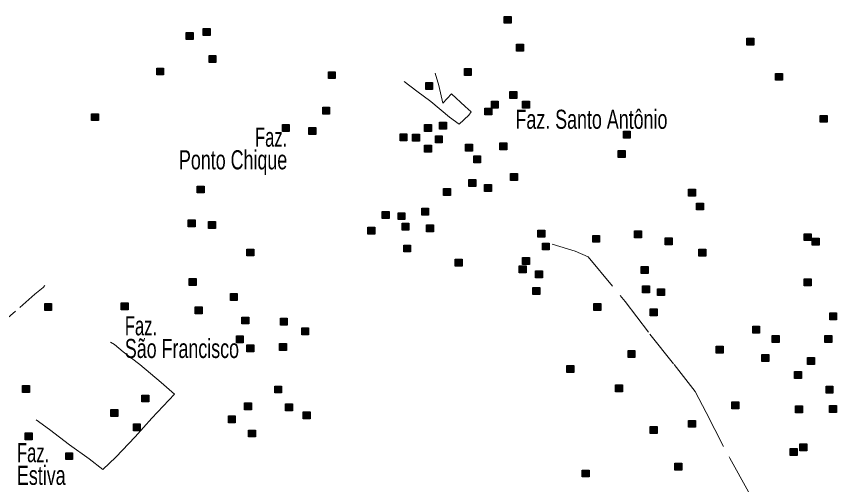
# Model space of a CAD drawing. Extents: x 445.6 to 500, y 8618.1 to 8673.4.
# Drawn here: x 456.65 to 463.53, y 8640.26 to 8644.2 of the extents above; entities that cross this region are included whole.
import ezdxf
from ezdxf.enums import TextEntityAlignment as Align

# ---------------------------------------------------------------- set-up
doc = ezdxf.new("R2010")
doc.units = 0
doc.header["$LTSCALE"] = 0.064
doc.linetypes.add('DOT_DASHED', pattern=[7.7, 5, -1.2, 0.3, -1.2])
doc.layers.add('2', color=7, linetype='Continuous', lineweight=25)
doc.layers.add('22', color=7, linetype='DOT_DASHED', lineweight=13)
doc.layers.add('61', color=7, linetype='Continuous')

msp = doc.modelspace()

# ---------------------------------------------------------------- hatches: boundary and pattern name
at = {"layer": '2'}
for points in [[(460.7425, 8644.196), (460.8005, 8644.196), (460.8005, 8644.138), (460.7425, 8644.138)], [(458.0774, 8644.0607), (458.1354, 8644.0607), (458.1354, 8644.0027), (458.0774, 8644.0027)], [(458.2193, 8644.0946), (458.2773, 8644.0946), (458.2773, 8644.0366), (458.2193, 8644.0366)], [(462.7768, 8644.0124), (462.8348, 8644.0124), (462.8348, 8643.9544), (462.7768, 8643.9544)], [(460.846, 8643.9624), (460.904, 8643.9624), (460.904, 8643.9044), (460.846, 8643.9044)], [(458.2681, 8643.8678), (458.3261, 8643.8678), (458.3261, 8643.8098), (458.2681, 8643.8098)], [(457.8289, 8643.7628), (457.8869, 8643.7628), (457.8869, 8643.7048), (457.8289, 8643.7048)], [(460.4086, 8643.7592), (460.4666, 8643.7592), (460.4666, 8643.7012), (460.4086, 8643.7012)], [(459.2679, 8643.7323), (459.3259, 8643.7323), (459.3259, 8643.6743), (459.2679, 8643.6743)], [(463.0168, 8643.7185), (463.0748, 8643.7185), (463.0748, 8643.6605), (463.0168, 8643.6605)], [(460.0843, 8643.6406), (460.1423, 8643.6406), (460.1423, 8643.5826), (460.0843, 8643.5826)], [(460.7903, 8643.5661), (460.8483, 8643.5661), (460.8483, 8643.5081), (460.7903, 8643.5081)], [(460.6349, 8643.4848), (460.6929, 8643.4848), (460.6929, 8643.4268), (460.6349, 8643.4268)], [(460.8967, 8643.4847), (460.9547, 8643.4847), (460.9547, 8643.4267), (460.8967, 8643.4267)], [(459.2206, 8643.4341), (459.2786, 8643.4341), (459.2786, 8643.3761), (459.2206, 8643.3761)], [(460.5808, 8643.4272), (460.6388, 8643.4272), (460.6388, 8643.3692), (460.5808, 8643.3692)], [(457.2832, 8643.3799), (457.3412, 8643.3799), (457.3412, 8643.3219), (457.2832, 8643.3219)], [(463.3918, 8643.3662), (463.4498, 8643.3662), (463.4498, 8643.3082), (463.3918, 8643.3082)], [(458.8828, 8643.2885), (458.9408, 8643.2885), (458.9408, 8643.2305), (458.8828, 8643.2305)], [(460.0742, 8643.2883), (460.1322, 8643.2883), (460.1322, 8643.2303), (460.0742, 8643.2303)], [(460.1992, 8643.3086), (460.2572, 8643.3086), (460.2572, 8643.2506), (460.1992, 8643.2506)], [(459.1057, 8643.2647), (459.1637, 8643.2647), (459.1637, 8643.2067), (459.1057, 8643.2067)], [(459.8691, 8643.2105), (459.9271, 8643.2105), (459.9271, 8643.1525), (459.8691, 8643.1525)], [(459.9743, 8643.2086), (460.0323, 8643.2086), (460.0323, 8643.1506), (459.9743, 8643.1506)], [(461.7411, 8643.234), (461.7991, 8643.234), (461.7991, 8643.176), (461.7411, 8643.176)], [(460.1654, 8643.1934), (460.2234, 8643.1934), (460.2234, 8643.1354), (460.1654, 8643.1354)], [(460.0742, 8643.1155), (460.1322, 8643.1155), (460.1322, 8643.0575), (460.0742, 8643.0575)], [(460.4189, 8643.1237), (460.4769, 8643.1237), (460.4769, 8643.0657), (460.4189, 8643.0657)], [(460.7058, 8643.1358), (460.7638, 8643.1358), (460.7638, 8643.0778), (460.7058, 8643.0778)], [(461.6972, 8643.0714), (461.7552, 8643.0714), (461.7552, 8643.0134), (461.6972, 8643.0134)], [(460.4865, 8643.0254), (460.5445, 8643.0254), (460.5445, 8642.9674), (460.4865, 8642.9674)], [(460.7954, 8642.8783), (460.8534, 8642.8783), (460.8534, 8642.8203), (460.7954, 8642.8203)], [(460.4457, 8642.8275), (460.5037, 8642.8275), (460.5037, 8642.7695), (460.4457, 8642.7695)], [(458.1681, 8642.7734), (458.2261, 8642.7734), (458.2261, 8642.7154), (458.1681, 8642.7154)], [(460.2329, 8642.753), (460.2909, 8642.753), (460.2909, 8642.695), (460.2329, 8642.695)], [(460.5775, 8642.7869), (460.6355, 8642.7869), (460.6355, 8642.7289), (460.5775, 8642.7289)], [(462.2873, 8642.7462), (462.3453, 8642.7462), (462.3453, 8642.6882), (462.2873, 8642.6882)], [(462.3548, 8642.631), (462.4128, 8642.631), (462.4128, 8642.573), (462.3548, 8642.573)], [(459.7205, 8642.5601), (459.7785, 8642.5601), (459.7785, 8642.5021), (459.7205, 8642.5021)], [(459.8522, 8642.5499), (459.9102, 8642.5499), (459.9102, 8642.4919), (459.8522, 8642.4919)], [(460.0505, 8642.587), (460.1085, 8642.587), (460.1085, 8642.529), (460.0505, 8642.529)], [(458.0938, 8642.4889), (458.1518, 8642.4889), (458.1518, 8642.4309), (458.0938, 8642.4309)], [(458.2627, 8642.4753), (458.3207, 8642.4753), (458.3207, 8642.4173), (458.2627, 8642.4173)], [(459.886, 8642.4618), (459.944, 8642.4618), (459.944, 8642.4038), (459.886, 8642.4038)], [(459.5989, 8642.4279), (459.6569, 8642.4279), (459.6569, 8642.3699), (459.5989, 8642.3699)], [(460.0911, 8642.4481), (460.1491, 8642.4481), (460.1491, 8642.3901), (460.0911, 8642.3901)], [(461.025, 8642.404), (461.083, 8642.404), (461.083, 8642.346), (461.025, 8642.346)], [(461.8357, 8642.3972), (461.8937, 8642.3972), (461.8937, 8642.3392), (461.8357, 8642.3392)], [(461.4844, 8642.36), (461.5424, 8642.36), (461.5424, 8642.302), (461.4844, 8642.302)], [(462.0913, 8642.3396), (462.1493, 8642.3396), (462.1493, 8642.2816), (462.0913, 8642.2816)], [(463.2567, 8642.3735), (463.3147, 8642.3735), (463.3147, 8642.3155), (463.2567, 8642.3155)], [(463.3242, 8642.3362), (463.3822, 8642.3362), (463.3822, 8642.2782), (463.3242, 8642.2782)], [(458.5856, 8642.245), (458.6436, 8642.245), (458.6436, 8642.187), (458.5856, 8642.187)], [(459.8995, 8642.2789), (459.9575, 8642.2789), (459.9575, 8642.2209), (459.8995, 8642.2209)], [(461.0622, 8642.2956), (461.1202, 8642.2956), (461.1202, 8642.2376), (461.0622, 8642.2376)], [(462.3751, 8642.2448), (462.4331, 8642.2448), (462.4331, 8642.1868), (462.3751, 8642.1868)], [(460.3309, 8642.1601), (460.3889, 8642.1601), (460.3889, 8642.1021), (460.3309, 8642.1021)], [(460.8967, 8642.1736), (460.9547, 8642.1736), (460.9547, 8642.1156), (460.8967, 8642.1156)], [(460.8687, 8642.1031), (460.9267, 8642.1031), (460.9267, 8642.0451), (460.8687, 8642.0451)], [(461.0048, 8642.0618), (461.0628, 8642.0618), (461.0628, 8642.0038), (461.0048, 8642.0038)], [(461.8917, 8642.0994), (461.9497, 8642.0994), (461.9497, 8642.0414), (461.8917, 8642.0414)], [(458.1021, 8641.9977), (458.1601, 8641.9977), (458.1601, 8641.9397), (458.1021, 8641.9397)], [(463.257, 8641.994), (463.315, 8641.994), (463.315, 8641.936), (463.257, 8641.936)], [(460.983, 8641.9228), (461.041, 8641.9228), (461.041, 8641.8648), (460.983, 8641.8648)], [(461.9019, 8641.9365), (461.9599, 8641.9365), (461.9599, 8641.8785), (461.9019, 8641.8785)], [(462.0269, 8641.9128), (462.0849, 8641.9128), (462.0849, 8641.8548), (462.0269, 8641.8548)], [(458.4466, 8641.8724), (458.5046, 8641.8724), (458.5046, 8641.8144), (458.4466, 8641.8144)], [(456.8904, 8641.7877), (456.9484, 8641.7877), (456.9484, 8641.7297), (456.8904, 8641.7297)], [(457.5322, 8641.7944), (457.5902, 8641.7944), (457.5902, 8641.7364), (457.5322, 8641.7364)], [(461.4932, 8641.7875), (461.5512, 8641.7875), (461.5512, 8641.7295), (461.4932, 8641.7295)], [(458.1528, 8641.7606), (458.2108, 8641.7606), (458.2108, 8641.7026), (458.1528, 8641.7026)], [(461.9652, 8641.743), (462.0232, 8641.743), (462.0232, 8641.685), (461.9652, 8641.685)], [(463.4708, 8641.7097), (463.5288, 8641.7097), (463.5288, 8641.6517), (463.4708, 8641.6517)], [(458.5434, 8641.6752), (458.6014, 8641.6752), (458.6014, 8641.6172), (458.5434, 8641.6172)], [(458.8655, 8641.6657), (458.9235, 8641.6657), (458.9235, 8641.6077), (458.8655, 8641.6077)], [(459.0445, 8641.5844), (459.1025, 8641.5844), (459.1025, 8641.5264), (459.0445, 8641.5264)], [(462.8257, 8641.5979), (462.8837, 8641.5979), (462.8837, 8641.5399), (462.8257, 8641.5399)], [(458.4973, 8641.5166), (458.5553, 8641.5166), (458.5553, 8641.4586), (458.4973, 8641.4586)], [(462.9895, 8641.5198), (463.0475, 8641.5198), (463.0475, 8641.4618), (462.9895, 8641.4618)], [(463.4303, 8641.5199), (463.4883, 8641.5199), (463.4883, 8641.4619), (463.4303, 8641.4619)], [(458.584, 8641.4412), (458.642, 8641.4412), (458.642, 8641.3832), (458.584, 8641.3832)], [(458.8587, 8641.4523), (458.9167, 8641.4523), (458.9167, 8641.3943), (458.8587, 8641.3943)], [(462.5198, 8641.431), (462.5778, 8641.431), (462.5778, 8641.373), (462.5198, 8641.373)], [(461.7803, 8641.3945), (461.8383, 8641.3945), (461.8383, 8641.3365), (461.7803, 8641.3365)], [(462.9034, 8641.3607), (462.9614, 8641.3607), (462.9614, 8641.3027), (462.9034, 8641.3027)], [(463.2846, 8641.3354), (463.3426, 8641.3354), (463.3426, 8641.2774), (463.2846, 8641.2774)], [(461.2669, 8641.2691), (461.3249, 8641.2691), (461.3249, 8641.2111), (461.2669, 8641.2111)], [(463.1753, 8641.2183), (463.2333, 8641.2183), (463.2333, 8641.1603), (463.1753, 8641.1603)], [(456.7046, 8641.0999), (456.7626, 8641.0999), (456.7626, 8641.0419), (456.7046, 8641.0419)], [(458.8182, 8641.0965), (458.8762, 8641.0965), (458.8762, 8641.0385), (458.8182, 8641.0385)], [(461.6756, 8641.1065), (461.7336, 8641.1065), (461.7336, 8641.0485), (461.6756, 8641.0485)], [(463.44, 8641.0948), (463.498, 8641.0948), (463.498, 8641.0368), (463.44, 8641.0368)], [(457.7048, 8641.0206), (457.7628, 8641.0206), (457.7628, 8640.9626), (457.7048, 8640.9626)], [(458.5649, 8640.9543), (458.6229, 8640.9543), (458.6229, 8640.8963), (458.5649, 8640.8963)], [(458.9094, 8640.9475), (458.9674, 8640.9475), (458.9674, 8640.8895), (458.9094, 8640.8895)], [(462.6518, 8640.9642), (462.7098, 8640.9642), (462.7098, 8640.9062), (462.6518, 8640.9062)], [(457.4444, 8640.8985), (457.5024, 8640.8985), (457.5024, 8640.8405), (457.4444, 8640.8405)], [(459.058, 8640.8797), (459.116, 8640.8797), (459.116, 8640.8217), (459.058, 8640.8217)], [(463.1855, 8640.9303), (463.2435, 8640.9303), (463.2435, 8640.8723), (463.1855, 8640.8723)], [(463.4704, 8640.9322), (463.5284, 8640.9322), (463.5284, 8640.8742), (463.4704, 8640.8742)], [(458.4298, 8640.8458), (458.4878, 8640.8458), (458.4878, 8640.7878), (458.4298, 8640.7878)], [(462.287, 8640.8084), (462.345, 8640.8084), (462.345, 8640.7504), (462.287, 8640.7504)], [(457.6335, 8640.7781), (457.6915, 8640.7781), (457.6915, 8640.7201), (457.6335, 8640.7201)], [(461.9671, 8640.756), (462.0251, 8640.756), (462.0251, 8640.698), (461.9671, 8640.698)], [(456.7266, 8640.7046), (456.7846, 8640.7046), (456.7846, 8640.6466), (456.7266, 8640.6466)], [(458.5986, 8640.7273), (458.6566, 8640.7273), (458.6566, 8640.6693), (458.5986, 8640.6693)], [(463.2209, 8640.612), (463.2789, 8640.612), (463.2789, 8640.554), (463.2209, 8640.554)], [(457.0661, 8640.5375), (457.1241, 8640.5375), (457.1241, 8640.4795), (457.0661, 8640.4795)], [(463.1398, 8640.5713), (463.1978, 8640.5713), (463.1978, 8640.5133), (463.1398, 8640.5133)], [(461.3952, 8640.3919), (461.4532, 8640.3919), (461.4532, 8640.3339), (461.3952, 8640.3339)], [(462.1721, 8640.4493), (462.2301, 8640.4493), (462.2301, 8640.3913), (462.1721, 8640.3913)]]:
    msp.add_hatch(color=256, dxfattribs=at).paths.add_polyline_path(points)

# ---------------------------------------------------------------- linework, layer by layer
for points in [[(460.7425, 8644.196), (460.8005, 8644.196), (460.8005, 8644.138), (460.7425, 8644.138)], [(458.0774, 8644.0607), (458.1354, 8644.0607), (458.1354, 8644.0027), (458.0774, 8644.0027)], [(458.2193, 8644.0946), (458.2773, 8644.0946), (458.2773, 8644.0366), (458.2193, 8644.0366)], [(462.7768, 8644.0124), (462.8348, 8644.0124), (462.8348, 8643.9544), (462.7768, 8643.9544)], [(460.846, 8643.9624), (460.904, 8643.9624), (460.904, 8643.9044), (460.846, 8643.9044)], [(458.2681, 8643.8678), (458.3261, 8643.8678), (458.3261, 8643.8098), (458.2681, 8643.8098)], [(457.8289, 8643.7628), (457.8869, 8643.7628), (457.8869, 8643.7048), (457.8289, 8643.7048)], [(460.4086, 8643.7592), (460.4666, 8643.7592), (460.4666, 8643.7012), (460.4086, 8643.7012)], [(459.2679, 8643.7323), (459.3259, 8643.7323), (459.3259, 8643.6743), (459.2679, 8643.6743)], [(463.0168, 8643.7185), (463.0748, 8643.7185), (463.0748, 8643.6605), (463.0168, 8643.6605)], [(460.0843, 8643.6406), (460.1423, 8643.6406), (460.1423, 8643.5826), (460.0843, 8643.5826)], [(460.7903, 8643.5661), (460.8483, 8643.5661), (460.8483, 8643.5081), (460.7903, 8643.5081)], [(460.6349, 8643.4848), (460.6929, 8643.4848), (460.6929, 8643.4268), (460.6349, 8643.4268)], [(460.8967, 8643.4847), (460.9547, 8643.4847), (460.9547, 8643.4267), (460.8967, 8643.4267)], [(459.2206, 8643.4341), (459.2786, 8643.4341), (459.2786, 8643.3761), (459.2206, 8643.3761)], [(460.5808, 8643.4272), (460.6388, 8643.4272), (460.6388, 8643.3692), (460.5808, 8643.3692)], [(457.2832, 8643.3799), (457.3412, 8643.3799), (457.3412, 8643.3219), (457.2832, 8643.3219)], [(463.3918, 8643.3662), (463.4498, 8643.3662), (463.4498, 8643.3082), (463.3918, 8643.3082)], [(458.8828, 8643.2885), (458.9408, 8643.2885), (458.9408, 8643.2305), (458.8828, 8643.2305)], [(460.0742, 8643.2883), (460.1322, 8643.2883), (460.1322, 8643.2303), (460.0742, 8643.2303)], [(460.1992, 8643.3086), (460.2572, 8643.3086), (460.2572, 8643.2506), (460.1992, 8643.2506)], [(459.1057, 8643.2647), (459.1637, 8643.2647), (459.1637, 8643.2067), (459.1057, 8643.2067)], [(459.8691, 8643.2105), (459.9271, 8643.2105), (459.9271, 8643.1525), (459.8691, 8643.1525)], [(459.9743, 8643.2086), (460.0323, 8643.2086), (460.0323, 8643.1506), (459.9743, 8643.1506)], [(461.7411, 8643.234), (461.7991, 8643.234), (461.7991, 8643.176), (461.7411, 8643.176)], [(460.1654, 8643.1934), (460.2234, 8643.1934), (460.2234, 8643.1354), (460.1654, 8643.1354)], [(460.0742, 8643.1155), (460.1322, 8643.1155), (460.1322, 8643.0575), (460.0742, 8643.0575)], [(460.4189, 8643.1237), (460.4769, 8643.1237), (460.4769, 8643.0657), (460.4189, 8643.0657)], [(460.7058, 8643.1358), (460.7638, 8643.1358), (460.7638, 8643.0778), (460.7058, 8643.0778)], [(461.6972, 8643.0714), (461.7552, 8643.0714), (461.7552, 8643.0134), (461.6972, 8643.0134)], [(460.4865, 8643.0254), (460.5445, 8643.0254), (460.5445, 8642.9674), (460.4865, 8642.9674)], [(460.7954, 8642.8783), (460.8534, 8642.8783), (460.8534, 8642.8203), (460.7954, 8642.8203)], [(460.4457, 8642.8275), (460.5037, 8642.8275), (460.5037, 8642.7695), (460.4457, 8642.7695)], [(458.1681, 8642.7734), (458.2261, 8642.7734), (458.2261, 8642.7154), (458.1681, 8642.7154)], [(460.2329, 8642.753), (460.2909, 8642.753), (460.2909, 8642.695), (460.2329, 8642.695)], [(460.5775, 8642.7869), (460.6355, 8642.7869), (460.6355, 8642.7289), (460.5775, 8642.7289)], [(462.2873, 8642.7462), (462.3453, 8642.7462), (462.3453, 8642.6882), (462.2873, 8642.6882)], [(462.3548, 8642.631), (462.4128, 8642.631), (462.4128, 8642.573), (462.3548, 8642.573)], [(459.7205, 8642.5601), (459.7785, 8642.5601), (459.7785, 8642.5021), (459.7205, 8642.5021)], [(459.8522, 8642.5499), (459.9102, 8642.5499), (459.9102, 8642.4919), (459.8522, 8642.4919)], [(460.0505, 8642.587), (460.1085, 8642.587), (460.1085, 8642.529), (460.0505, 8642.529)], [(458.0938, 8642.4889), (458.1518, 8642.4889), (458.1518, 8642.4309), (458.0938, 8642.4309)], [(458.2627, 8642.4753), (458.3207, 8642.4753), (458.3207, 8642.4173), (458.2627, 8642.4173)], [(459.886, 8642.4618), (459.944, 8642.4618), (459.944, 8642.4038), (459.886, 8642.4038)], [(459.5989, 8642.4279), (459.6569, 8642.4279), (459.6569, 8642.3699), (459.5989, 8642.3699)], [(460.0911, 8642.4481), (460.1491, 8642.4481), (460.1491, 8642.3901), (460.0911, 8642.3901)], [(461.025, 8642.404), (461.083, 8642.404), (461.083, 8642.346), (461.025, 8642.346)], [(461.8357, 8642.3972), (461.8937, 8642.3972), (461.8937, 8642.3392), (461.8357, 8642.3392)], [(461.4844, 8642.36), (461.5424, 8642.36), (461.5424, 8642.302), (461.4844, 8642.302)], [(462.0913, 8642.3396), (462.1493, 8642.3396), (462.1493, 8642.2816), (462.0913, 8642.2816)], [(463.2567, 8642.3735), (463.3147, 8642.3735), (463.3147, 8642.3155), (463.2567, 8642.3155)], [(463.3242, 8642.3362), (463.3822, 8642.3362), (463.3822, 8642.2782), (463.3242, 8642.2782)], [(458.5856, 8642.245), (458.6436, 8642.245), (458.6436, 8642.187), (458.5856, 8642.187)], [(459.8995, 8642.2789), (459.9575, 8642.2789), (459.9575, 8642.2209), (459.8995, 8642.2209)], [(461.0622, 8642.2956), (461.1202, 8642.2956), (461.1202, 8642.2376), (461.0622, 8642.2376)], [(462.3751, 8642.2448), (462.4331, 8642.2448), (462.4331, 8642.1868), (462.3751, 8642.1868)], [(460.3309, 8642.1601), (460.3889, 8642.1601), (460.3889, 8642.1021), (460.3309, 8642.1021)], [(460.8967, 8642.1736), (460.9547, 8642.1736), (460.9547, 8642.1156), (460.8967, 8642.1156)], [(460.8687, 8642.1031), (460.9267, 8642.1031), (460.9267, 8642.0451), (460.8687, 8642.0451)], [(461.0048, 8642.0618), (461.0628, 8642.0618), (461.0628, 8642.0038), (461.0048, 8642.0038)], [(461.8917, 8642.0994), (461.9497, 8642.0994), (461.9497, 8642.0414), (461.8917, 8642.0414)], [(458.1021, 8641.9977), (458.1601, 8641.9977), (458.1601, 8641.9397), (458.1021, 8641.9397)], [(463.257, 8641.994), (463.315, 8641.994), (463.315, 8641.936), (463.257, 8641.936)], [(460.983, 8641.9228), (461.041, 8641.9228), (461.041, 8641.8648), (460.983, 8641.8648)], [(461.9019, 8641.9365), (461.9599, 8641.9365), (461.9599, 8641.8785), (461.9019, 8641.8785)], [(462.0269, 8641.9128), (462.0849, 8641.9128), (462.0849, 8641.8548), (462.0269, 8641.8548)], [(458.4466, 8641.8724), (458.5046, 8641.8724), (458.5046, 8641.8144), (458.4466, 8641.8144)], [(456.8904, 8641.7877), (456.9484, 8641.7877), (456.9484, 8641.7297), (456.8904, 8641.7297)], [(457.5322, 8641.7944), (457.5902, 8641.7944), (457.5902, 8641.7364), (457.5322, 8641.7364)], [(461.4932, 8641.7875), (461.5512, 8641.7875), (461.5512, 8641.7295), (461.4932, 8641.7295)], [(458.1528, 8641.7606), (458.2108, 8641.7606), (458.2108, 8641.7026), (458.1528, 8641.7026)], [(461.9652, 8641.743), (462.0232, 8641.743), (462.0232, 8641.685), (461.9652, 8641.685)], [(463.4708, 8641.7097), (463.5288, 8641.7097), (463.5288, 8641.6517), (463.4708, 8641.6517)], [(458.5434, 8641.6752), (458.6014, 8641.6752), (458.6014, 8641.6172), (458.5434, 8641.6172)], [(458.8655, 8641.6657), (458.9235, 8641.6657), (458.9235, 8641.6077), (458.8655, 8641.6077)], [(459.0445, 8641.5844), (459.1025, 8641.5844), (459.1025, 8641.5264), (459.0445, 8641.5264)], [(462.8257, 8641.5979), (462.8837, 8641.5979), (462.8837, 8641.5399), (462.8257, 8641.5399)], [(458.4973, 8641.5166), (458.5553, 8641.5166), (458.5553, 8641.4586), (458.4973, 8641.4586)], [(462.9895, 8641.5198), (463.0475, 8641.5198), (463.0475, 8641.4618), (462.9895, 8641.4618)], [(463.4303, 8641.5199), (463.4883, 8641.5199), (463.4883, 8641.4619), (463.4303, 8641.4619)], [(458.584, 8641.4412), (458.642, 8641.4412), (458.642, 8641.3832), (458.584, 8641.3832)], [(458.8587, 8641.4523), (458.9167, 8641.4523), (458.9167, 8641.3943), (458.8587, 8641.3943)], [(462.5198, 8641.431), (462.5778, 8641.431), (462.5778, 8641.373), (462.5198, 8641.373)], [(461.7803, 8641.3945), (461.8383, 8641.3945), (461.8383, 8641.3365), (461.7803, 8641.3365)], [(462.9034, 8641.3607), (462.9614, 8641.3607), (462.9614, 8641.3027), (462.9034, 8641.3027)], [(463.2846, 8641.3354), (463.3426, 8641.3354), (463.3426, 8641.2774), (463.2846, 8641.2774)], [(461.2669, 8641.2691), (461.3249, 8641.2691), (461.3249, 8641.2111), (461.2669, 8641.2111)], [(463.1753, 8641.2183), (463.2333, 8641.2183), (463.2333, 8641.1603), (463.1753, 8641.1603)], [(456.7046, 8641.0999), (456.7626, 8641.0999), (456.7626, 8641.0419), (456.7046, 8641.0419)], [(458.8182, 8641.0965), (458.8762, 8641.0965), (458.8762, 8641.0385), (458.8182, 8641.0385)], [(461.6756, 8641.1065), (461.7336, 8641.1065), (461.7336, 8641.0485), (461.6756, 8641.0485)], [(463.44, 8641.0948), (463.498, 8641.0948), (463.498, 8641.0368), (463.44, 8641.0368)], [(457.7048, 8641.0206), (457.7628, 8641.0206), (457.7628, 8640.9626), (457.7048, 8640.9626)], [(458.5649, 8640.9543), (458.6229, 8640.9543), (458.6229, 8640.8963), (458.5649, 8640.8963)], [(458.9094, 8640.9475), (458.9674, 8640.9475), (458.9674, 8640.8895), (458.9094, 8640.8895)], [(462.6518, 8640.9642), (462.7098, 8640.9642), (462.7098, 8640.9062), (462.6518, 8640.9062)], [(457.4444, 8640.8985), (457.5024, 8640.8985), (457.5024, 8640.8405), (457.4444, 8640.8405)], [(459.058, 8640.8797), (459.116, 8640.8797), (459.116, 8640.8217), (459.058, 8640.8217)], [(463.1855, 8640.9303), (463.2435, 8640.9303), (463.2435, 8640.8723), (463.1855, 8640.8723)], [(463.4704, 8640.9322), (463.5284, 8640.9322), (463.5284, 8640.8742), (463.4704, 8640.8742)], [(458.4298, 8640.8458), (458.4878, 8640.8458), (458.4878, 8640.7878), (458.4298, 8640.7878)], [(462.287, 8640.8084), (462.345, 8640.8084), (462.345, 8640.7504), (462.287, 8640.7504)], [(457.6335, 8640.7781), (457.6915, 8640.7781), (457.6915, 8640.7201), (457.6335, 8640.7201)], [(461.9671, 8640.756), (462.0251, 8640.756), (462.0251, 8640.698), (461.9671, 8640.698)], [(456.7266, 8640.7046), (456.7846, 8640.7046), (456.7846, 8640.6466), (456.7266, 8640.6466)], [(458.5986, 8640.7273), (458.6566, 8640.7273), (458.6566, 8640.6693), (458.5986, 8640.6693)], [(463.2209, 8640.612), (463.2789, 8640.612), (463.2789, 8640.554), (463.2209, 8640.554)], [(457.0661, 8640.5375), (457.1241, 8640.5375), (457.1241, 8640.4795), (457.0661, 8640.4795)], [(463.1398, 8640.5713), (463.1978, 8640.5713), (463.1978, 8640.5133), (463.1398, 8640.5133)], [(461.3952, 8640.3919), (461.4532, 8640.3919), (461.4532, 8640.3339), (461.3952, 8640.3339)], [(462.1721, 8640.4493), (462.2301, 8640.4493), (462.2301, 8640.3913), (462.1721, 8640.3913)]]:
    msp.add_lwpolyline(points, close=True, dxfattribs=at)
at = {"layer": '22'}
for points in [[(459.9037, 8643.6512), (460.0103, 8643.5704), (460.1267, 8643.4833), (460.2845, 8643.3505), (460.3634, 8643.2924), (460.4445, 8643.3671), (460.4652, 8643.3962), (460.4154, 8643.4397), (460.3011, 8643.5476), (460.2264, 8643.4688), (460.1931, 8643.6161), (460.1638, 8643.7205)], [(461.1443, 8642.2859), (461.336, 8642.2272), (461.4474, 8642.1809), (461.7568, 8641.804), (461.9641, 8641.5321), (462.1662, 8641.2768), (462.3426, 8641.0513), (462.4354, 8640.8752), (462.6337, 8640.4902), (462.8039, 8640.1844), (462.8879, 8640.022), (462.8969, 8639.9862)], [(456.401, 8641.5166), (456.6822, 8641.7551), (456.8077, 8641.8678), (456.8769, 8641.9235), (456.8919, 8641.9381)], [(456.8193, 8640.8134), (456.9298, 8640.7312), (457.0991, 8640.6029), (457.262, 8640.4871), (457.3779, 8640.3963), (457.4876, 8640.4996), (457.6474, 8640.6718), (457.7884, 8640.8282), (457.9796, 8641.0285), (457.8668, 8641.1256), (457.6882, 8641.2758), (457.5471, 8641.3822), (457.4751, 8641.4448), (457.4425, 8641.465)]]:
    msp.add_lwpolyline(points, dxfattribs=at)

# ---------------------------------------------------------------- texts
at = {"layer": '61'}
for s, width, p in [('Faz. Santo Antônio', 0.7, (460.8367, 8643.2534)), ('Faz.', 0.65, (457.5619, 8641.5214)), ('São Francisco', 0.7, (457.5619, 8641.3314)), ('Faz.', 0.65, (456.6576, 8640.4579)), ('Estiva', 0.7, (456.6576, 8640.2679))]:
    msp.add_text(s, height=0.16, dxfattribs=dict(at, width=width)).set_placement(p)
for s, width, p in [('Faz.', 0.65, (458.9234, 8643.1034)), ('Ponto Chique', 0.7, (458.9234, 8642.9134))]:
    msp.add_text(s, height=0.16, dxfattribs=dict(at, width=width)).set_placement(p, align=Align.RIGHT)

doc.saveas('drawing.dxf')
